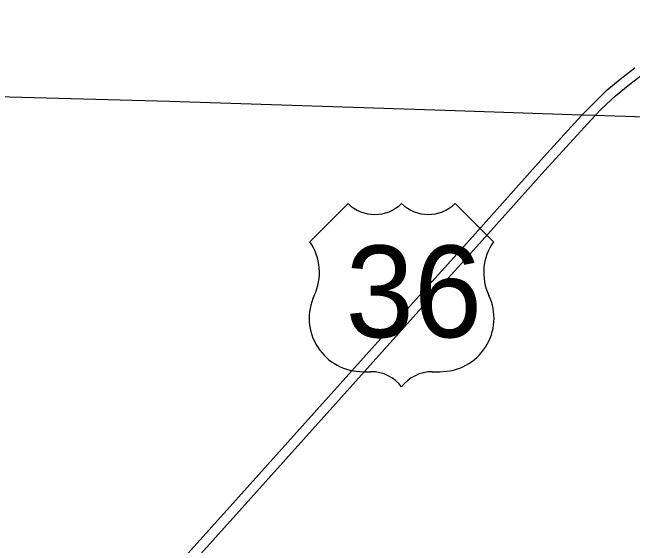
# Model space of a CAD drawing. Extents: x -6.3 to 34, y 0 to 22.
# Drawn here: x 6.643 to 7.254, y 13.107 to 13.632 of the extents above; entities that cross this region are included whole.
import ezdxf

# ---------------------------------------------------------------- set-up
doc = ezdxf.new("R2010")
doc.units = 0
for name, color, linetype in [('GM_X_Township', 7, 'Continuous'), ('GM_X_US_Route', 7, 'Continuous'), ('GM_X_US_Shield', 7, 'Continuous')]:
    doc.layers.add(name, color=color, linetype=linetype)

msp = doc.modelspace()

# ---------------------------------------------------------------- linework, layer by layer
at = {"layer": 'GM_X_Township'}
msp.add_lwpolyline([(7.48685, 13.52147), (7.21634, 13.53039), (7.20335, 13.53081), (7.07915, 13.53508), (6.79804, 13.54416), (6.56764, 13.55052), (6.53915, 13.55118), (6.16647, 13.55477)], dxfattribs=at)
at = {"layer": 'GM_X_US_Route'}
for points in [[(7.10015, 13.40114), (7.16752, 13.47628), (7.21648, 13.53002), (7.22318, 13.537), (7.23687, 13.5498), (7.25101, 13.56141), (7.26381, 13.57108), (7.28529, 13.58509), (7.29685, 13.59147), (7.31426, 13.6004), (7.33227, 13.60829), (7.34968, 13.61469), (7.36783, 13.62034), (7.38837, 13.62525), (7.40593, 13.62853), (7.42632, 13.63106), (7.43942, 13.6318), (7.45073, 13.6318), (7.46725, 13.63195), (7.48645, 13.63046), (7.5052, 13.62838), (7.52752, 13.62451), (7.54821, 13.61945), (7.55844, 13.61663)], [(7.09608, 13.41095), (7.16611, 13.48926), (7.20349, 13.53044), (7.22868, 13.55561), (7.24312, 13.56736), (7.25607, 13.57748)], [(6.51688, 12.78861), (6.51865, 12.7929), (6.5229, 12.79748), (6.53681, 12.80658), (6.55467, 12.81967), (6.57535, 12.83634), (6.59098, 12.85063), (6.62015, 12.87995), (6.64396, 12.90673), (6.6633, 12.92817), (6.759, 13.03472), (6.81347, 13.09604), (6.86585, 13.15438), (6.97465, 13.27552), (7.03492, 13.34294), (7.09608, 13.41095)], [(6.6465, 12.895), (6.66298, 12.91356), (6.76466, 13.02698), (6.86949, 13.14386), (6.9673, 13.25293), (7.06612, 13.36319), (7.10015, 13.40114)]]:
    msp.add_lwpolyline(points, dxfattribs=at)
at = {"layer": 'GM_X_US_Shield'}
for p, q in [((6.97371, 13.44373), (6.93607, 13.40608)), ((7.11677, 13.40608), (7.07912, 13.44373)), ((6.98877, 13.27808), (6.9963, 13.27808)), ((7.05653, 13.27808), (7.06406, 13.27808))]:
    msp.add_line(p, q, dxfattribs=at)
for centre, radius, start, end in [((7.00006, 13.47061), 0.03765, 225.573, 314.427), ((7.05277, 13.47061), 0.03765, 225.573, 314.427), ((6.89289, 13.37585), 0.05271, 334.54712, 35.00093), ((7.15994, 13.37585), 0.05271, 144.99907, 205.45288), ((6.98818, 13.33079), 0.05271, 154.83192, 270.63826), ((7.06465, 13.33079), 0.05271, 269.36174, 25.16808), ((6.9963, 13.24044), 0.03765, 36.8699, 90), ((7.05653, 13.24044), 0.03765, 90, 143.1301)]:
    msp.add_arc(centre, radius, start, end, dxfattribs=at)

# ---------------------------------------------------------------- texts
msp.add_text('36', height=0.090352, dxfattribs=at).set_placement((6.97131, 13.31197))

doc.saveas('drawing.dxf')
